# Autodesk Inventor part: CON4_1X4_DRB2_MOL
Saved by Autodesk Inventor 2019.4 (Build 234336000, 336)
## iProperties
Created: 2021-02
Part Number: CON4_1X4_DRB2_MOL
Material: Generic
Document SubType Name: Modeling
Designer: Administrator
Density: 1 g/cm^3
Appearance: Default
Title: CON4_1X4_DRB2_MOL
Author: Administrator
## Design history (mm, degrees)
feature "Body1"
body "Solid1"
